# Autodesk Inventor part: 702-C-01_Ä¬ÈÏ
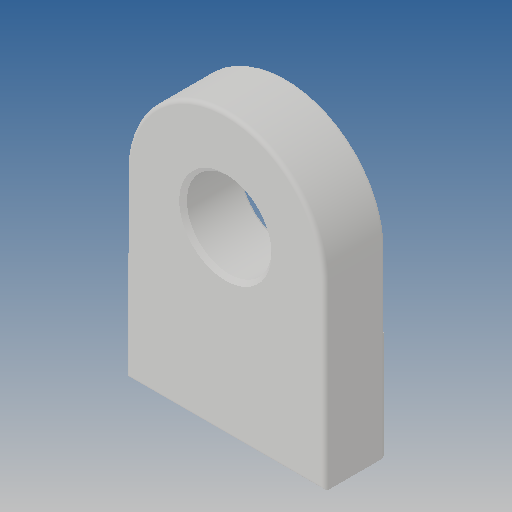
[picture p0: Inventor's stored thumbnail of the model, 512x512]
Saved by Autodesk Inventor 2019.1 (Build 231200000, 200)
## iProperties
Created: 2010-06
Part Number: 702-C-01_Ä¬ÈÏ
Material: Ogólny
Document SubType Name: Modeling
Designer: CADENGINEERING4
Density: 1 g/cm^3
Appearance: Domyślna
Author: CADENGINEERING4
Revision Number: ÈÎºÎ
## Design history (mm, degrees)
feature "NONE"
node "Bryła1"
